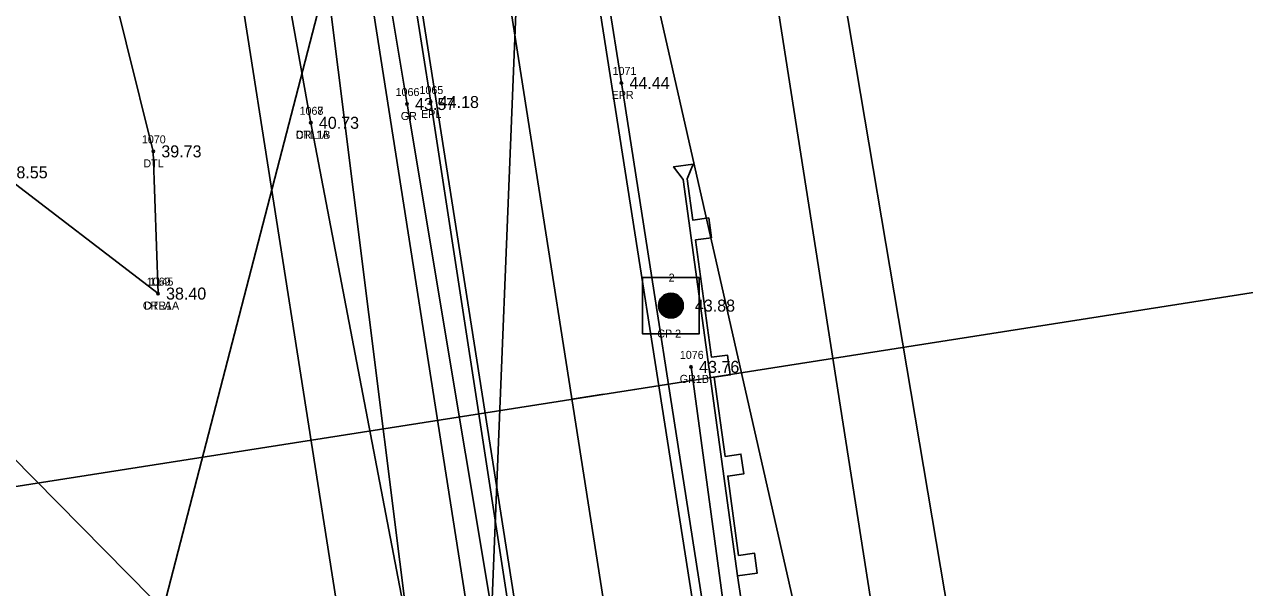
# Model space of a CAD drawing. Extents: x 2619568 to 2620316, y 784340 to 785138.
# Drawn here: x 2619755.9 to 2619908.4, y 784874.9 to 784945.3 of the extents above; entities that cross this region are included whole.
import ezdxf

# ---------------------------------------------------------------- set-up
doc = ezdxf.new("R2010")
doc.units = 0
for name, color, linetype in [('RD_EX_GuardRail', 7, 'Continuous'), ('RD_EX_GuardRail_txCode', 7, 'Continuous'), ('RD_EX_H2O', 7, 'Continuous'), ('RD_EX_H2O_txCode', 7, 'Continuous'), ('RD_EX_Road', 7, 'Continuous'), ('RD_EX_Road_txCode', 7, 'Continuous'), ('RD_EX_RW', 7, 'Continuous'), ('RD_EX_TX_GuardRail_ELEV', 7, 'Continuous'), ('RD_EX_TX_H2O_ELEV', 7, 'Continuous'), ('RD_EX_TX_Road_ELEV', 7, 'Continuous'), ('RD_EX_VEG', 7, 'Continuous'), ('RD_HC_Cl', 7, 'Continuous'), ('RD_HC_Data_Tic', 7, 'Continuous'), ('RD_HC_Survey', 7, 'Continuous'), ('RD_HC_Survey_ELEV', 7, 'Continuous'), ('RD_HC_Survey_txCode', 7, 'Continuous'), ('RD_PD_Final_TrvlWay', 7, 'Continuous'), ('RD_PD_GR', 7, 'Continuous'), ('RD_PD_PatLn1', 7, 'Continuous'), ('RD_PD_PatLn2', 7, 'Continuous'), ('RD_SMD_Locator', 7, 'Continuous')]:
    doc.layers.add(name, color=color, linetype=linetype)

msp = doc.modelspace()

# ---------------------------------------------------------------- linework, layer by layer
at = {"layer": 'RD_EX_GuardRail'}
for points in [[(2619867.12, 784523.3), (2619850.86, 784633.15), (2619824.72, 784807.66), (2619818.35, 784847.92), (2619803.75, 784935.38), (2619787.81, 785031.17), (2619775.16, 785106.97)], [(2619898.96, 784529.78), (2619881.94, 784636.77), (2619850.55, 784824.95), (2619844.25, 784865.7), (2619839.24, 784902.52)]]:
    msp.add_lwpolyline(points, dxfattribs=at)
at = {"layer": 'RD_EX_H2O'}
for points in [[(2619772.64, 784911.68), (2619772.05, 784929.46), (2619748.39, 785024.59), (2619738.12, 785085.25), (2619757.14, 785100.38)], [(2619791.73, 784933.03), (2619763.93, 785088.41), (2619762.47, 785100.82), (2619757.14, 785100.38)], [(2619772.64, 784911.68), (2619752.83, 784926.84), (2619712.83, 784937.52), (2619673.24, 784936.72), (2619647.77, 784928.32), (2619603.54, 784903.62)], [(2619819.63, 784843.41), (2619811.5, 784844.43), (2619805.32, 784862.13), (2619791.73, 784933.03)], [(2619773.83, 784850.15), (2619780.57, 784864.79), (2619733.81, 784912.21), (2619700.27, 784924.63), (2619672.07, 784923.77), (2619649.36, 784903.37), (2619624.57, 784890.48)]]:
    msp.add_lwpolyline(points, dxfattribs=at)
at = {"layer": 'RD_EX_Road'}
for p, q in [((2619806.71, 784935.63), (2619791.64, 785032.01)), ((2619830.54, 784938.02), (2619815.78, 785030.4)), ((2619841.88, 784865.21), (2619830.54, 784938.02)), ((2619820.6, 784845.48), (2619806.71, 784935.63))]:
    msp.add_line(p, q, dxfattribs=at)
at = {"layer": 'RD_EX_RW'}
for p, q in [((2619822.1, 785125.87), (2619915.04, 784533.11)), ((2619756.9, 785115.64), (2619849.84, 784522.89))]:
    msp.add_line(p, q, dxfattribs=at)
at = {"layer": 'RD_EX_VEG'}
for points in [[(2619930.82, 784519.47), (2619827.3, 785132.88)], [(2619857.01, 784520.73), (2619804.77, 784862.84), (2619772.02, 785124.21)]]:
    msp.add_lwpolyline(points, dxfattribs=at)
at = {"layer": 'RD_HC_Cl'}
msp.add_line((2619789.5, 785120.76), (2619882.44, 784528), dxfattribs=at)
at = {"layer": 'RD_HC_Data_Tic'}
msp.add_line((2619824.35, 784898.47), (2619828.3, 784899.09), dxfattribs=at)
at = {"layer": 'RD_HC_Survey'}
for p, q in [((2619835.6, 784909.09), (2619835.6, 784911.26)), ((2619835.65, 784909.04), (2619835.65, 784911.31)), ((2619835.7, 784909), (2619835.7, 784911.36)), ((2619835.75, 784908.95), (2619835.75, 784911.4)), ((2619835.8, 784908.92), (2619835.8, 784911.43)), ((2619835.85, 784908.88), (2619835.85, 784911.47)), ((2619835.9, 784908.85), (2619835.9, 784911.5)), ((2619835.95, 784908.82), (2619835.95, 784911.53)), ((2619836, 784908.79), (2619836, 784911.56)), ((2619836.05, 784908.77), (2619836.05, 784911.58)), ((2619836.1, 784908.75), (2619836.1, 784911.6)), ((2619836.15, 784908.73), (2619836.15, 784911.63)), ((2619836.2, 784908.71), (2619836.2, 784911.64)), ((2619836.25, 784908.69), (2619836.25, 784911.66)), ((2619836.3, 784908.68), (2619836.3, 784911.67)), ((2619836.35, 784908.66), (2619836.35, 784911.69)), ((2619836.4, 784908.65), (2619836.4, 784911.7)), ((2619836.45, 784908.64), (2619836.45, 784911.71)), ((2619836.5, 784908.64), (2619836.5, 784911.72)), ((2619836.55, 784908.63), (2619836.55, 784911.72)), ((2619836.6, 784908.63), (2619836.6, 784911.73)), ((2619836.65, 784908.62), (2619836.65, 784911.73)), ((2619836.7, 784908.62), (2619836.7, 784911.73)), ((2619836.75, 784908.62), (2619836.75, 784911.73)), ((2619836.8, 784908.62), (2619836.8, 784911.73)), ((2619836.85, 784908.63), (2619836.85, 784911.72)), ((2619836.9, 784908.63), (2619836.9, 784911.72)), ((2619836.95, 784908.64), (2619836.95, 784911.71)), ((2619837, 784908.65), (2619837, 784911.7)), ((2619837.05, 784908.66), (2619837.05, 784911.69)), ((2619837.1, 784908.67), (2619837.1, 784911.68)), ((2619837.15, 784908.68), (2619837.15, 784911.67)), ((2619837.2, 784908.7), (2619837.2, 784911.65)), ((2619837.25, 784908.72), (2619837.25, 784911.63)), ((2619837.3, 784908.74), (2619837.3, 784911.61)), ((2619837.35, 784908.76), (2619837.35, 784911.59)), ((2619837.4, 784908.78), (2619837.4, 784911.57)), ((2619837.45, 784908.81), (2619837.45, 784911.54)), ((2619837.5, 784908.84), (2619837.5, 784911.52)), ((2619837.55, 784908.87), (2619837.55, 784911.48)), ((2619837.6, 784908.9), (2619837.6, 784911.45)), ((2619837.65, 784908.94), (2619837.65, 784911.42)), ((2619837.7, 784908.98), (2619837.7, 784911.38)), ((2619837.75, 784909.02), (2619837.75, 784911.33)), ((2619837.8, 784909.07), (2619837.8, 784911.29)), ((2619837.85, 784909.12), (2619837.85, 784911.23)), ((2619835.2, 784909.81), (2619835.2, 784910.54)), ((2619835.25, 784909.65), (2619835.25, 784910.7)), ((2619835.3, 784909.52), (2619835.3, 784910.83)), ((2619835.35, 784909.43), (2619835.35, 784910.93)), ((2619835.4, 784909.34), (2619835.4, 784911.01)), ((2619835.45, 784909.27), (2619835.45, 784911.08)), ((2619835.5, 784909.2), (2619835.5, 784911.15)), ((2619835.55, 784909.14), (2619835.55, 784911.21)), ((2619837.9, 784909.17), (2619837.9, 784911.18)), ((2619837.95, 784909.24), (2619837.95, 784911.12)), ((2619838, 784909.31), (2619838, 784911.05)), ((2619838.05, 784909.38), (2619838.05, 784910.97)), ((2619838.1, 784909.48), (2619838.1, 784910.88)), ((2619838.15, 784909.59), (2619838.15, 784910.77)), ((2619838.2, 784909.73), (2619838.2, 784910.63)), ((2619838.25, 784909.95), (2619838.25, 784910.4))]:
    msp.add_line(p, q, dxfattribs=at)
msp.add_lwpolyline([(2619840.24, 784913.71), (2619833.17, 784913.71), (2619833.17, 784906.64), (2619840.24, 784906.64)], close=True, dxfattribs=at)
msp.add_circle((2619836.71, 784910.18), 1.55, dxfattribs=at)
at = {"layer": 'RD_PD_Final_TrvlWay'}
for p, q in [((2619804.24, 785097.76), (2619881.69, 784603.8)), ((2619782.51, 785094.35), (2619859.95, 784600.39))]:
    msp.add_line(p, q, dxfattribs=at)
at = {"layer": 'RD_PD_GR'}
for p, q in [((2619851.12, 784617.98), (2619784.32, 785044.03)), ((2619845.02, 784876.41), (2619879.87, 784654.12))]:
    msp.add_line(p, q, dxfattribs=at)
msp.add_lwpolyline([(2619838.26, 784925.95), (2619845.02, 784876.41), (2619847.5, 784876.74), (2619847.16, 784879.22), (2619845.17, 784878.95), (2619843.82, 784888.86), (2619845.81, 784889.13), (2619845.47, 784891.61), (2619843.48, 784891.33), (2619842.13, 784901.24), (2619844.12, 784901.51), (2619843.78, 784903.99), (2619841.79, 784903.72), (2619839.79, 784918.38), (2619841.78, 784918.66), (2619841.44, 784921.13), (2619839.45, 784920.86), (2619838.75, 784926.01), (2619839.51, 784927.87), (2619837.04, 784927.53)], close=True, dxfattribs=at)
at = {"layer": 'RD_PD_PatLn1'}
msp.add_line((2619972.54, 784921.71), (2619676.16, 784875.24), dxfattribs=at)
at = {"layer": 'RD_PD_PatLn2'}
for p, q in [((2619801.18, 784980.03), (2619725.97, 784689.61)), ((2619828.58, 784976.51), (2619894.93, 784683.94)), ((2619818.47, 784975.2), (2619806.39, 784675.45))]:
    msp.add_line(p, q, dxfattribs=at)
at = {"layer": 'RD_SMD_Locator'}
for centre in [(2619830.54, 784938.02), (2619806.71, 784935.63), (2619803.75, 784935.38), (2619791.73, 784933.03), (2619791.73, 784933.03), (2619772.05, 784929.46), (2619772.64, 784911.68), (2619772.64, 784911.68), (2619836.71, 784910.18), (2619839.24, 784902.52)]:
    msp.add_circle(centre, 0.15, dxfattribs=at)

# ---------------------------------------------------------------- texts
at = {"layer": 'RD_EX_GuardRail_txCode'}
for s, p in [('1066', (2619802.32, 784936.38)), ('GR', (2619802.97, 784933.38)), ('1076', (2619837.83, 784903.52)), ('GR1B', (2619837.82, 784900.52))]:
    msp.add_text(s, height=1, dxfattribs=at).set_placement(p)
at = {"layer": 'RD_EX_H2O_txCode'}
for s, p in [('1067', (2619790.32, 784934.03)), ('1068', (2619790.32, 784934.03)), ('1070', (2619770.62, 784930.46)), ('CRL1B', (2619789.86, 784931.03)), ('DTL1A', (2619789.83, 784931.03)), ('DTL', (2619770.81, 784927.46)), ('1069', (2619771.23, 784912.68)), ('1145', (2619771.58, 784912.68)), ('CRR1A', (2619770.74, 784909.68)), ('DTLA', (2619770.91, 784909.68))]:
    msp.add_text(s, height=1, dxfattribs=at).set_placement(p)
at = {"layer": 'RD_EX_Road_txCode'}
for s, p in [('1071', (2619829.43, 784939.02)), ('1065', (2619805.3, 784936.63)), ('EPR', (2619829.31, 784936.02)), ('EPL', (2619805.51, 784933.63))]:
    msp.add_text(s, height=1, dxfattribs=at).set_placement(p)
at = {"layer": 'RD_EX_TX_GuardRail_ELEV'}
for s, p in [('43.57', (2619804.75, 784934.63)), ('43.76', (2619840.24, 784901.77))]:
    msp.add_text(s, height=1.5, dxfattribs=at).set_placement(p)
at = {"layer": 'RD_EX_TX_H2O_ELEV'}
for s, p in [('40.73', (2619792.73, 784932.28)), ('40.73', (2619792.73, 784932.28)), ('39.73', (2619773.05, 784928.71)), ('38.55', (2619753.83, 784926.09)), ('38.40', (2619773.64, 784910.93)), ('38.40', (2619773.64, 784910.93))]:
    msp.add_text(s, height=1.5, dxfattribs=at).set_placement(p)
at = {"layer": 'RD_EX_TX_Road_ELEV'}
for s, p in [('44.44', (2619831.54, 784937.27)), ('44.18', (2619807.71, 784934.88))]:
    msp.add_text(s, height=1.5, dxfattribs=at).set_placement(p)
at = {"layer": 'RD_HC_Survey_ELEV'}
msp.add_text('43.88', height=1.5, dxfattribs=at).set_placement((2619839.71, 784909.43))
at = {"layer": 'RD_HC_Survey_txCode'}
for s, p in [('2', (2619836.43, 784913.18)), ('CP 2', (2619835.01, 784906.18))]:
    msp.add_text(s, height=1, dxfattribs=at).set_placement(p)

doc.saveas('drawing.dxf')
